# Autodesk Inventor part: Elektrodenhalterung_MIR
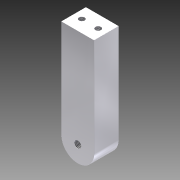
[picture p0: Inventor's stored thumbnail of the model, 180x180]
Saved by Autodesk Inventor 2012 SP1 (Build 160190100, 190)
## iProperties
Created: 2012-10
Part Number: Elektrodenhalterung_MIR
Material: Default
Document SubType Name: Modeling
Designer: Dominic Mähling
Density: 1 g/cm^3
Author: Dominic Mähling
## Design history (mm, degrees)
derived "Elektrodenhalterung.ipt"
feature "Volumenkörper1::Elektrodenhalterung.ipt" dims "d0" = 10
tag "Bezeichnung1"
node "Volumenkörper1"
